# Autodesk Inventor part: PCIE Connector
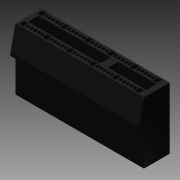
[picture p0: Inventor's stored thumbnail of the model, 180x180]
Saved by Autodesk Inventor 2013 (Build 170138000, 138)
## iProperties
Company: Autodesk Inc.
Created: 2005-12
Part Number: PCIE Connector
Document SubType Name: Modeling
Designer: Autodesk Inc.
Density: 1 g/cm^3
Mass: 1.09695 g
Surface Area: 21.9884 cm^2
Volume: 1.09695 cm^3
Material: Allgemein
Title: Personal Computer
Author: Autodesk Inc.
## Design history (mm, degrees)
sketch "Sketch1"
  geometry: L1 (0, 3.5)-(0, -3.5) reference; L2 (-17.5, 0)-(17.5, 0) reference; L3 (-12.5, 2.5)-(12.5, 2.5); L4 (12.5, 2.5)-(12.5, -2.5); L5 (12.5, -2.5)-(-12.5, -2.5); L6 (-12.5, -2.5)-(-12.5, 2.5)
  constraints: 8 end point, 2 parallel, 1 horizontal, 1 perpendicular, 2 other
  dimensions: "d0" = 25 distance of L3.start L3.end; "d1" = 5 distance of L5.end L3.start
extrude "Extrusion1" new body sketch "Sketch1" distance "d2" = 12; taper "d3" = 0 deg
sketch "Sketch2"
  geometry: L1 (12.5, 2.5)-(12.5, -2.5) reference; L2 (-12.5, -2.5)-(-12.5, 2.5) reference; L3 (-12.5, 0)-(12.5, 0); L4 (-11.5, 1)-(2.5, 1); L5 (2.5, 1)-(2.5, -1); L6 (2.5, -1)-(-11.5, -1); L7 (-11.5, -1)-(-11.5, 1); L8 (4, 1)-(11.5, 1); L9 (11.5, 1)-(11.5, -1); L10 (11.5, -1)-(4, -1); L11 (4, -1)-(4, 1)
  constraints: 18 end point, 4 parallel, 2 horizontal, 2 midpoint, 2 perpendicular, 1 collinear, 2 other
  dimensions: "d4" = 1 distance between parallel lines of L2 L7; "d5" = 2 distance of L6.end L4.start; "d6" = 14 distance of L4.start L4.end; "d7" = 1.5 distance between parallel lines of L11 L5; "d8" = 1 distance between parallel lines of L1 L9; "d9" = 7.5 distance of L8.start L8.end (derived)
extrude "Extrusion2" cut sketch "Sketch2" distance "d10" = 8; taper "d11" = 0 deg
sketch "Sketch3" dims "d23" = 10
  geometry: L1 (-11.5, 1)-(2.5, 1) reference; L2 (-12.5, 2.5)-(12.5, 2.5) reference; L3 (-12.5, -2.5)-(-12.5, 2.5) reference; L4 (-27.25, 2.5)-(-27.25, 1); L5 (-27.25, 1.75)-(-12.5, 1.75); L6 (-12, 2.25)-(-11.2, 2.25); L7 (-11.2, 2.25)-(-11.2, 1.25); L8 (-11.2, 1.25)-(-12, 1.25); L9 (-12, 1.25)-(-12, 2.25); L10 (-11, 2.05)-(-10.5, 2.05); L11 (-10.5, 2.05)-(-10.5, 1.45); L12 (-10.5, 1.45)-(-11, 1.45); L13 (-11, 1.45)-(-11, 2.05); L14 (-10.3, 2.05)-(-9.8, 2.05); L15 (-9.8, 2.05)-(-9.8, 1.45); L16 (-10.3, 1.45)-(-10.3, 2.05); L17 (-9.8, 1.45)-(-10.3, 1.45); L18 (-9.6, 2.05)-(-9.1, 2.05); L19 (-9.1, 2.05)-(-9.1, 1.45); L20 (-9.6, 1.45)-(-9.6, 2.05); L21 (-9.1, 1.45)-(-9.6, 1.45); L22 (-8.9, 2.05)-(-8.4, 2.05); L23 (-8.4, 2.05)-(-8.4, 1.45); L24 (-8.9, 1.45)-(-8.9, 2.05); L25 (-8.4, 1.45)-(-8.9, 1.45); L26 (-8.2, 2.05)-(-7.7, 2.05); L27 (-7.7, 2.05)-(-7.7, 1.45); L28 (-8.2, 1.45)-(-8.2, 2.05); L29 (-7.7, 1.45)-(-8.2, 1.45)
  constraints: 52 end point, 4 parallel, 4 perpendicular, 3 horizontal, 3 point on line, 1 midpoint, 34 other
  dimensions: "d12" = 0.8 distance of L6.start L6.end; "d13" = 1 distance of L8.end L6.start; "d14" = 0.2 distance between parallel lines of L7 L13; "d15" = 0.5 distance between parallel lines of L3 L9; "d16" = 0.5 distance of L10.start L10.end; "d17" = 0.6 distance of L10.end L11.end; "d20" = 0.7 distance of L10.start L14.start
extrude "Extrusion3" cut sketch "Sketch3" distance "d25" = 5; taper "d26" = 0 deg
pattern_linear "Rectangular Pattern1" dims "d29" = 4.5, "d32" = 1
sketch "Sketch5"
  geometry: L1 (10.3, 2.05)-(10.3, 1.45) reference; L2 (6, 2.25)-(6.8, 2.25) reference; L3 (6.8, 1.25)-(6, 1.25) reference; L4 (10.5, 2.25)-(11.3, 2.25); L5 (11.3, 2.25)-(11.3, 1.25); L6 (11.3, 1.25)-(10.5, 1.25); L7 (10.5, 1.25)-(10.5, 2.25)
  constraints: 8 end point, 2 collinear, 2 parallel, 1 horizontal, 1 perpendicular
  dimensions: "d37" = 0.2 distance between parallel lines of L7 L1; "d38" = 0.8 distance of L4.start L4.end
extrude "Extrusion5" cut sketch "Sketch5" distance "d39" = 8; taper "d40" = 0 deg
mirror "Mirror2"
sketch "Sketch6"
  geometry: L1 (0, 0)-(-12, 0) reference; L2 (0, 5)-(-12, 5) reference; L3 (-12, 0)-(-7.5, -1); L4 (-7.5, -1)-(-7, -1); L5 (-7, -1)-(-7, 0)
  constraints: 6 end point, 1 parallel, 1 perpendicular, 1 point on line
  dimensions: "d41" = 1 distance between parallel lines of L4 L1; "d42" = 4.5 horizontal distance of L1.end L3.end; "d43" = 0.5 distance of L3.end L4.end
extrude "Extrusion6" join sketch "Sketch6" stored distance "d44" = 8; taper "d45" = 0 deg
body "Solid1"
